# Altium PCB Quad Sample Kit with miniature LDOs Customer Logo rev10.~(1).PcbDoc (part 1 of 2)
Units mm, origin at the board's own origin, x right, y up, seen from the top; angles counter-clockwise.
Board outline 152.4 x 101.6 mm, 2 copper layers (Top Layer, Bottom Layer); 23 components, 21 nets, 109 pads, 47 vias.
Unrouted connection lines stored in the file: 13.
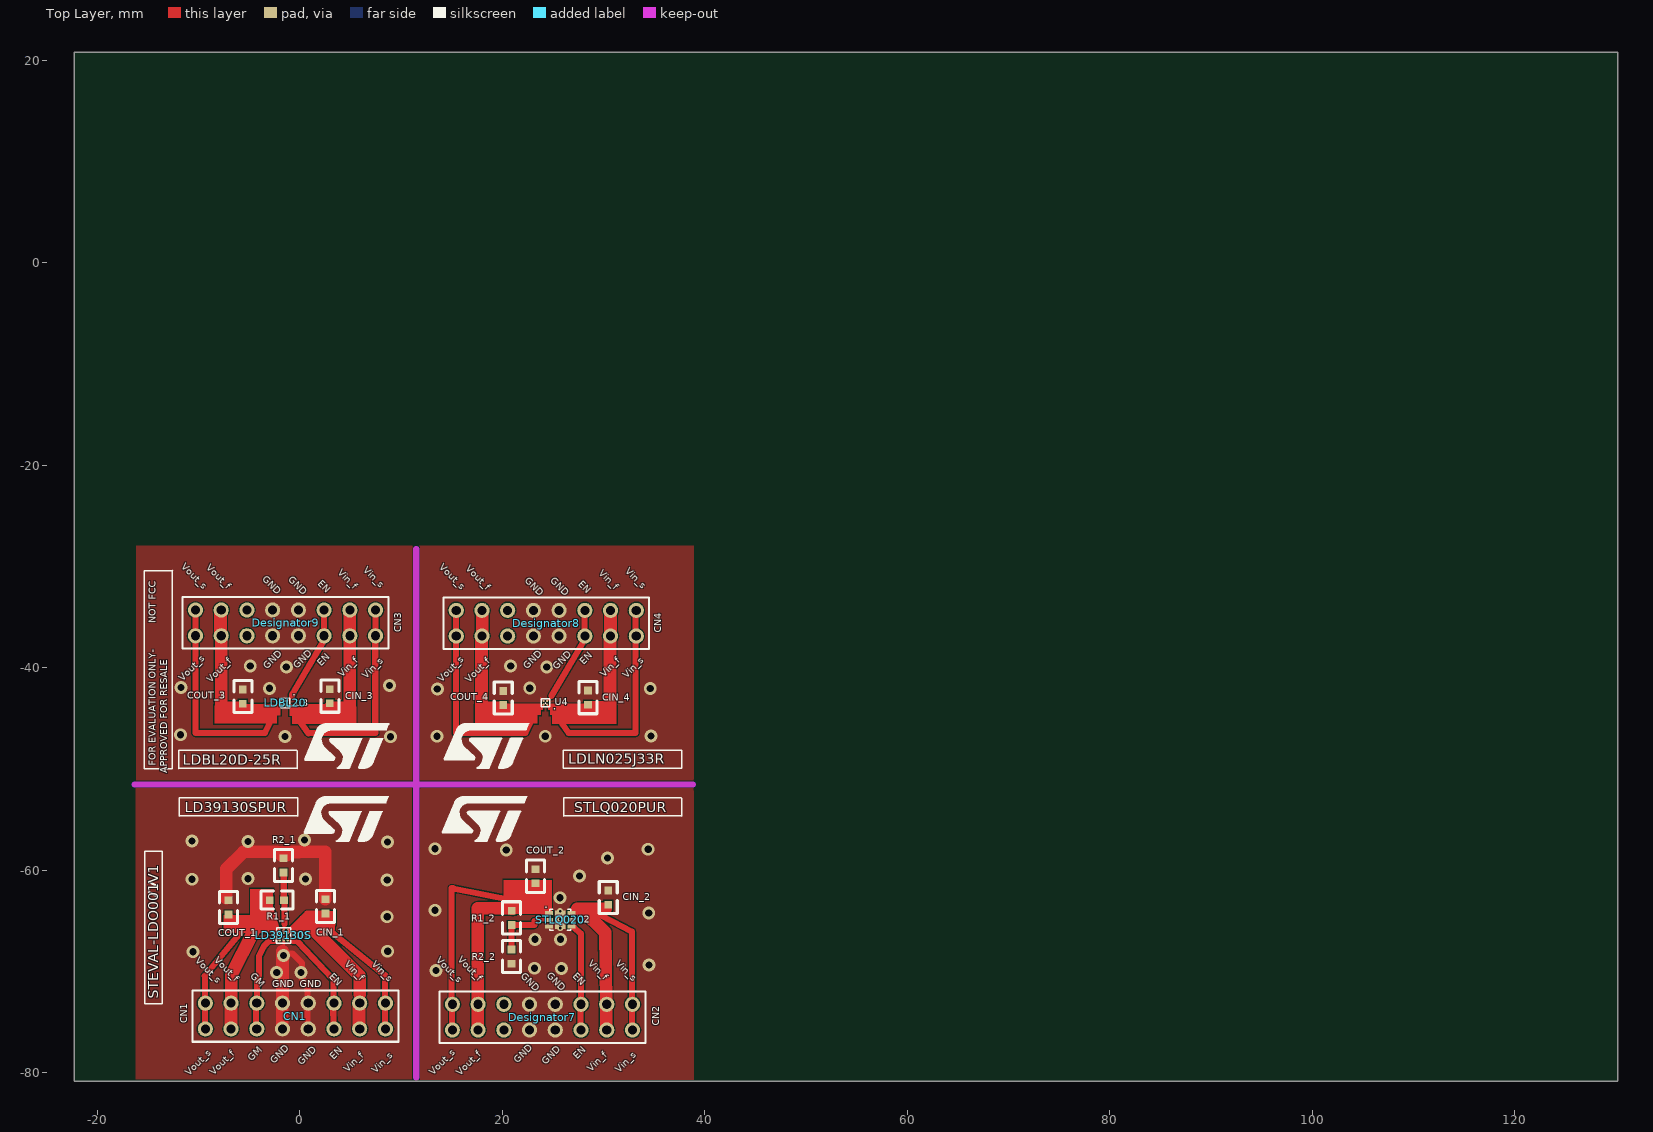
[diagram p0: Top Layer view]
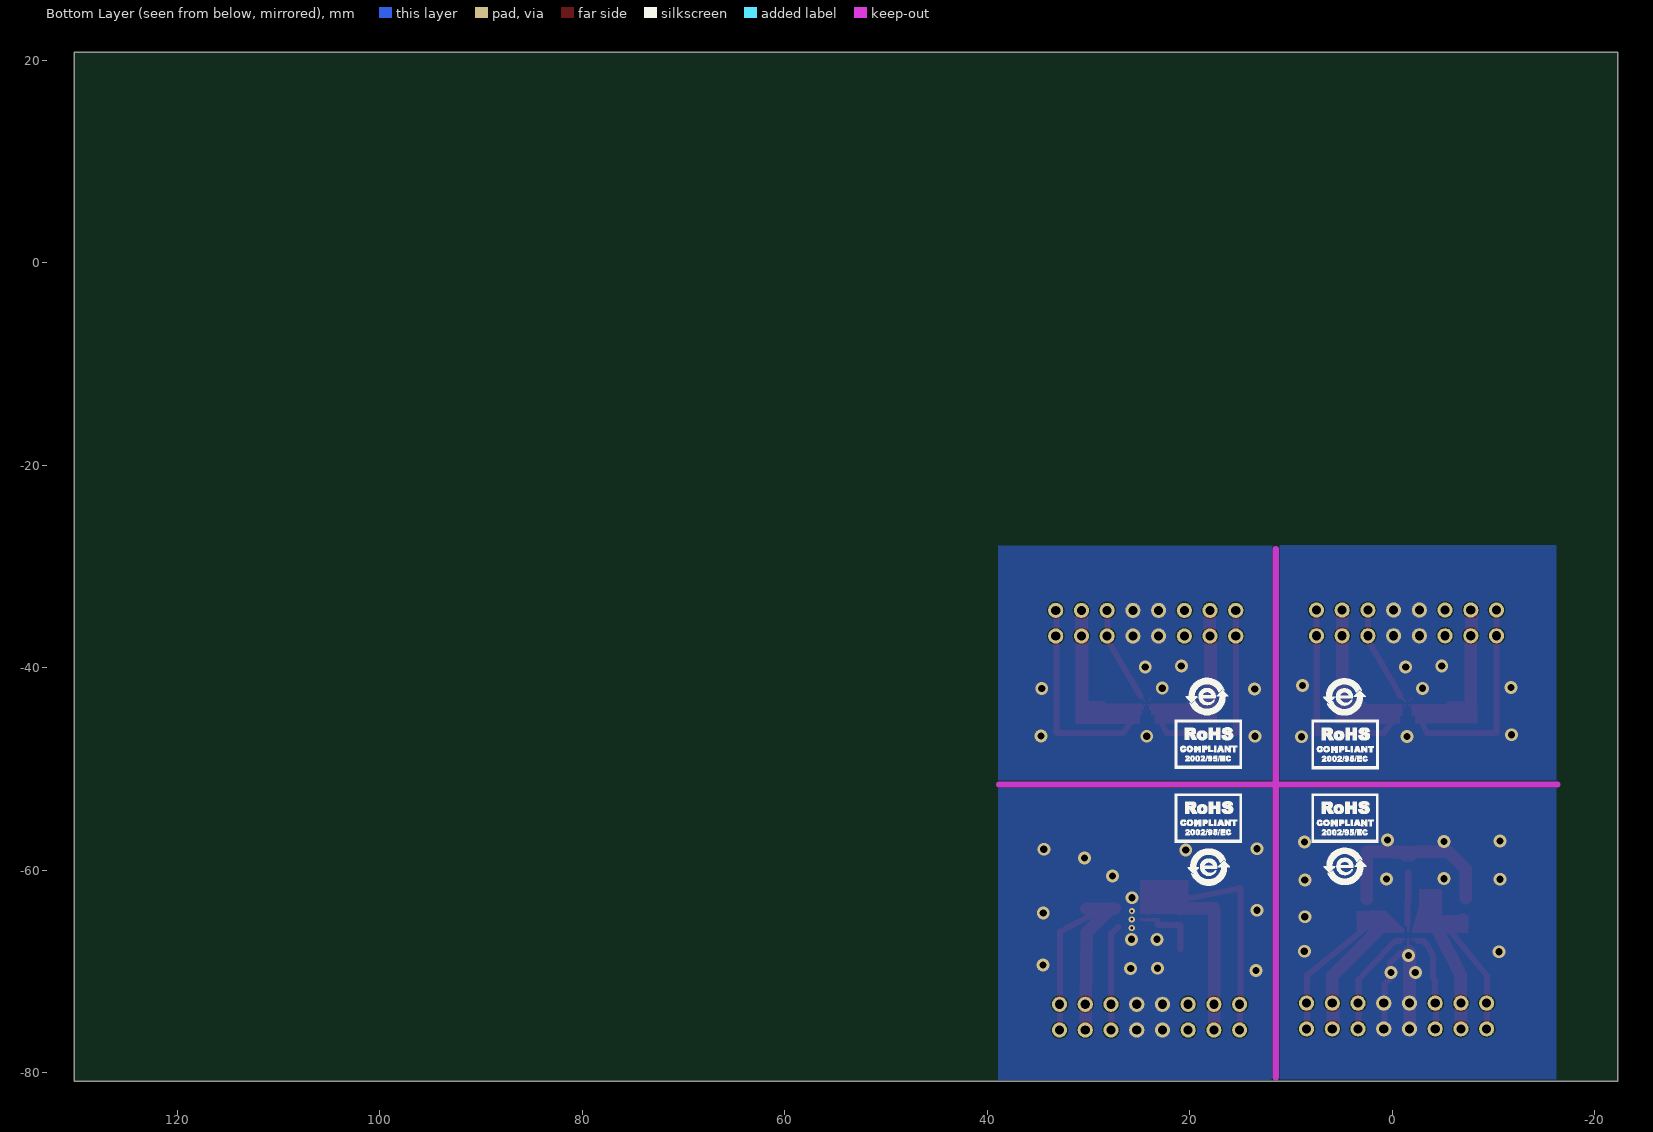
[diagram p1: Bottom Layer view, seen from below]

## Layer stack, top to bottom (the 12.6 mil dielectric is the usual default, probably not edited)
Top Layer: signal copper 0.0356
Dielectric: dielectric 0.32, FR-4, Dk 4.8
Bottom Layer: signal copper 0.0356

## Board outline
-22.247,-80.823 130.153,-80.823 130.153,20.777 -22.247,20.777

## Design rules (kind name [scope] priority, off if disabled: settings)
Clearance Clearance_1 [All] p1: gap=0.1
Clearance [All] p2: gap=0.1
ComponentClearance [All] p1: gap=0.254 collisioncheckmode=3 verticalgap=0.254
PolygonConnect [All] p1: connectstyle=Direct reliefconductorwidth=0.254 reliefentries=4 polygonreliefangle="90 Angle"
RoutingVias [All] p1: holewidth=0.711 width=1.27 viastyle="Through Hole" minholewidth=0.25 minwidth=0.25 maxholewidth=1 maxwidth=1.27
SolderMaskExpansion [All] p1: expansion=-0.035
TestPointUsage [All] p1: valid=0 allowmultiple=FALSE
Testpoint [All] p1: side=15 testpointundercomponent=TRUE minsize=1.016 maxsize=2.54 preferedsize=1.524 minholesize=0 maxholesize=1.016 preferedholesize=0.813 testpointgrid=0.025 style=1023 order=0123456789
Width [All] p1: maxlimit=2 minlimit=0.154 preferedwidth=0.254 minimp=50.000000 maximp=50.000000 favimp=50.000000
18 further rules are at their usual default settings.

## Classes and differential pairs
component class "Quad Sample Kit with miniature LDOs": CIN_1 CIN_2 CIN_3 CIN_4 Connector_1 Connector_2 Connector_3 Connector_4 COUT_1 COUT_2 COUT_3 COUT_4 LD39130S LDBL20 LDLN025J33R R1_1 R1_2 R2_1 R2_2 STLQ020

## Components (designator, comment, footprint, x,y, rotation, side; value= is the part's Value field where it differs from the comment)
CIN_1 "Cap" 0603 2.56,-63.562 r270 top
CIN_2 "Cap" 0603 30.478,-62.685 r270 top
CIN_3 "Cap" 0603 2.985,-42.804 r270 top
CIN_4 "Cap" 0603 28.472,-42.949 r270 top
CN1 "Comment" HDR2X8 -9.306,-75.655 r0 top
COUT_1 "Cap" 0603 -7.016,-63.664 r270 top
COUT_2 "Cap" 0603 23.284,-60.58 r270 top
COUT_3 "Cap" 0603 -5.608,-42.843 r270 top
COUT_4 "Cap" 0603 20.106,-42.983 r270 top
Designator7 "Comment" HDR2X8 15.086,-75.766 r0 top
Designator8 "Comment" HDR2X8 15.465,-36.867 r0 top
Designator9 "Comment" HDR2X8 -10.281,-36.84 r0 top
LD39130S "DFN6" PCBComponent_1#1 -1.178,-66.788 r0 top (schematic designator LD391303S)
LDBL20 "STSTAMP" PCBComponent_1#2 -1.253,-43.649 r0 top
R1_1 "Res1" 0603 -2.243,-62.939 r180 top
R1_2 "Res1" 0603 20.943,-64.692 r90 top
R2_1 "Res1" 0603 -1.585,-59.514 r270 top
R2_2 "Res1" 0603 20.923,-68.518 r270 top
STLQ020 "DFN6 2x2" PCBComponent_1#3 24.639,-64.882 r270 top
? "Comment" "LOGO_2014_10mm - duplicate" 13.544,-52.738 r0 top
? "Comment" "LOGO_2014_10mm - duplicate" 13.749,-45.529 r0 top
? "Comment" "LOGO_2014_10mm - duplicate" -0.11,-52.75 r0 top
? "Comment" "LOGO_2014_10mm - duplicate" -0.059,-45.55 r0 top

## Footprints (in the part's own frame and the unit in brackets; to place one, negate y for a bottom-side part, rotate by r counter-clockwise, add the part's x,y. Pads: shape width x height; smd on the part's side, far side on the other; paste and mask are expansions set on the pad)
0603 [mil]
  rect 30x30 smd: 1(-27.5,0) 2(27.48,0)
  silkscreen extent -63,-35 63,35
HDR2X8 [mm] "Connector; Header; 8x2 Position"
  round 1.5 hole 0.9: 1(0,0) 2(0,2.54) 3(2.54,0) 4(2.54,2.54) 5(5.08,0) 6(5.08,2.54) 7(7.62,0) 8(7.62,2.54) 9(10.16,0) 10(10.16,2.54) 11(12.7,0) 12(12.7,2.54) 13(15.24,0) 14(15.24,2.54) 15(17.78,0) 16(17.78,2.54)
  silkscreen extent -1.27,-1.27 19.05,3.81
"LOGO_2014_10mm - duplicate" [mm] "10mm sensa scritta"
  silkscreen extent 0.55,-4.37 8.89,0.07
PCBComponent_1#1 [mm]
  oct 0.25x0.475 smd: 0(-0.8,0) 0(-0.8,0.725) 0(-0.4,0) 0(-0.4,0.725) 0(0,0) 0(0,0.725)
PCBComponent_1#2 [mm]
  rect 0.25x0.25 smd: 0(-0.35,0) 0(-0.35,0.35) 0(0,0) 0(0,0.35)
PCBComponent_1#3 [mm]
  rect 0.4x0.8 smd: 0(-0.65,2.2) 0(-0.65,0) 0(0,2.2) 0(0,0) 0(0.65,2.2) 0(0.65,0)
  rect 1.8x1 smd: 1(0,1.1)

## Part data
CIN_1 CIN_2 CIN_3 CIN_4 COUT_1 COUT_2 COUT_3 COUT_4: "Capacitor"
CN1 Designator7 Designator8 Designator9: library part "Header 8X2"
LDBL20 STLQ020: library part Component_1
R1_1 R1_2 R2_1 R2_2: "Resistor"

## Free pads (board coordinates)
  round 0.181 smd: 1(24.094,-43.629) 1(24.094,-43.279) 1(24.444,-43.629) 1(24.444,-43.279)

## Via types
v1: diameter 1.27, hole 0.711, Top Layer to Bottom Layer, 44 vias
v2: diameter 0.6, hole 0.25, Top Layer to Bottom Layer, 3 vias

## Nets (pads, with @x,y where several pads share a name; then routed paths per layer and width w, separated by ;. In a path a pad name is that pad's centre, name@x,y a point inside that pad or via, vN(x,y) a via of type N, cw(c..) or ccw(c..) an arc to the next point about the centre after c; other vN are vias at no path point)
ADJ: LD39130S.0@-1.578,-66.063 R1_1.1 R1_2.1 R2_1.2 R2_2.1 STLQ020.0@24.639,-64.882 | length 15.1
  Top Layer w0.25: LD39130S.0@-1.577,-66.017 R1_1.1@-1.577,-62.989
  Top Layer w0.254: R1_1.1@-1.72,-62.717 -1.72,-62.681 R1_1.1@-1.72,-62.677 ; R1_1.1@-1.568,-62.941 -1.565,-62.932 R1_1.1@-1.555,-62.901 ; R1_2.1@20.822,-65.402 20.908,-65.382 R1_2.1@20.939,-65.375 ; R1_2.1@20.946,-65.39 20.946,-65.385 R1_2.1@20.946,-65.375 ; STLQ020.0@24.639,-64.869 STLQ020.0@24.813,-64.871
  Top Layer w0.35: 23.267,-64.875 STLQ020.0@24.637,-64.875
  Top Layer w0.6: R1_1.1@-1.568,-63.021 R2_1.2@-1.568,-60.194 ; R1_1.1@-1.568,-62.992 -1.479,-62.992 -1.479,-65.302 ; R1_2.1@20.909,-65.385 23.182,-65.385 23.182,-65.025 ; R2_2.1@20.928,-67.799 R1_2.1@20.928,-65.39
EN: CN1.11 CN1.12 Designator7.11 Designator7.12 Designator8.11 Designator8.12 Designator9.11 Designator9.12 LD39130S.0@-1.178,-66.788 LDBL20.0@-1.253,-43.299 pad.1@24.444,-43.279 STLQ020.0@26.839,-65.532 | length 40.9
  Top Layer w0.181: pad.1@24.444,-43.279 24.714,-43.015
  Top Layer w0.25: LDBL20.0@-1.253,-43.299 -0.668,-42.767
  Top Layer w0.254: LD39130S.0@-1.161,-66.787 -0.385,-66.787 ; -0.43,-66.779 -0.422,-66.788 ; Designator9.11@2.365,-37.305 Designator9.11@2.372,-37.303 ; Designator9.11@2.373,-37.303 2.395,-37.297 Designator9.11@2.408,-37.293 ; Designator9.11@2.381,-37.335 Designator9.11@2.381,-37.333 ; Designator9.11@2.393,-37.336 Designator9.11@2.398,-37.307 ; 3.34,-70.771 3.414,-70.85 ; STLQ020.0@26.893,-65.625 STLQ020.0@27.074,-65.61
  Top Layer w0.6: -0.771,-42.758 -0.732,-42.712 -0.718,-42.696 -0.648,-42.614 ; -0.757,-42.655 Designator9.11@2.388,-37.333 ; -0.715,-66.991 -0.216,-67.005 3.34,-70.77 ; Designator9.11@2.336,-36.796 Designator9.11@2.409,-36.723 ; Designator9.11@2.411,-36.774 Designator9.12@2.411,-34.312 ; CN1.12@3.322,-73.045 3.323,-73.116 CN1.11@3.343,-75.634 ; 3.339,-70.727 3.34,-70.77 ; CN1.12@3.347,-72.881 3.347,-72.85 3.34,-70.85 3.34,-70.771 ; 24.853,-42.796 Designator8.11@28.09,-37.318 ; STLQ020.0@27.074,-65.61 27.775,-66.257 Designator7.12@27.775,-72.98 ; Designator7.11@27.738,-75.77 Designator7.12@27.738,-73.252 ; Designator8.12@28.081,-34.249 Designator8.12@28.084,-34.33 ; Designator8.11@28.145,-36.873 Designator8.12@28.145,-34.336
GM: CN1.5 CN1.6 LD39130S.0@-1.978,-66.788 | length 10
  Top Layer w0.254: CN1.6@-4.215,-72.854 CN1.6@-4.215,-72.692 ; -2.507,-66.959 -2.465,-66.788 LD39130S.0@-1.997,-66.788
  Top Layer w0.6: CN1.5@-4.297,-75.634 -4.297,-73.116 CN1.6@-4.297,-73.108 ; CN1.6@-4.215,-72.692 -4.212,-70.809 -4.015,-70.612 -4.015,-68.466 ; -4.022,-68.55 -4.015,-68.535 -3.527,-67.491 -2.995,-66.959 -2.507,-66.959
GND: CIN_1.1 CIN_2.1 CIN_3.1 CIN_4.1 CN1.7 CN1.8 CN1.9 CN1.10 COUT_1.1 COUT_2.1 COUT_3.1 COUT_4.1 Designator7.7 Designator7.8 Designator7.9 Designator7.10 Designator8.7 Designator8.8 Designator8.9 Designator8.10 Designator9.7 Designator9.8 Designator9.9 Designator9.10 LD39130S.0@-1.578,-66.788 LDBL20.0@-1.603,-43.299 pad.1@24.094,-43.279 R2_1.1 R2_2.2 STLQ020.0@24.639,-65.532 STLQ020.1 | length 37.2
  Top Layer w0.181: -1.931,-42.984 LDBL20.0@-1.603,-43.299 ; 23.808,-42.986 pad.1@24.091,-43.276
  Top Layer w0.25: -1.578,-67.546 LD39130S.0@-1.578,-66.745
  Top Layer w0.254: COUT_1.1@-7.074,-62.979 -7.07,-62.972 COUT_1.1@-7.053,-62.944 ; COUT_1.1@-6.997,-63.018 -6.997,-62.98 COUT_1.1@-6.997,-62.966 ; CN1.8@-1.696,-72.851 CN1.8@-1.696,-72.847 ; R2_1.1@-1.604,-58.828 R2_1.1@-1.585,-58.828 ; R2_1.1@-1.601,-58.821 R2_1.1@-1.585,-58.821 ; CN1.8@-1.585,-72.919 -1.585,-72.898 -1.585,-72.85 CN1.8@-1.585,-72.847
  Top Layer w0.6: v1@-1.778,-68.202 -0.708,-68.202 0.25,-69.16 0.25,-70.723 0.795,-71.268 CN1.10@0.795,-72.914 ; CN1.10@0.77,-73.114 CN1.9@0.775,-75.571 ; CN1.10@0.818,-73.114 CN1.10@0.818,-73.087
  Top Layer w1.25: COUT_1.1@-7.238,-62.724 -7.238,-59.863 -5.552,-58.177 -2.245,-58.177 -2.225,-58.197 -0.711,-58.197 ; R2_1.1@-1.78,-58.518 -1.282,-58.518 -0.938,-58.174 ; CN1.8@-1.729,-73.108 -1.729,-73.115 CN1.7@-1.708,-75.634 ; CN1.8@-1.685,-72.803 v1@-1.685,-68.004 ; -0.925,-58.185 -0.064,-58.185 ; -0.064,-58.177 2.536,-58.177 ; CIN_1.1@2.536,-62.863 2.536,-58.328
  other v1: -2.266,-70.085 0.133,-70.091 13.475,-69.901 23.189,-69.661 25.845,-69.685 34.511,-69.353 -1.587,-68.403 -10.529,-68.035 8.695,-67.993 23.238,-66.81 25.772,-66.81 8.647,-64.576 34.48,-64.21 13.373,-63.938 25.713,-62.712 8.647,-60.944 -10.631,-60.879 0.577,-60.865 -5.09,-60.822 27.629,-60.56 30.393,-58.775 20.407,-57.979 34.418,-57.921 13.373,-57.872 8.671,-57.193 -5.085,-57.14 -10.631,-57.096 0.475,-57.002 8.965,-46.807 -1.456,-46.778 13.576,-46.759 24.253,-46.761 34.695,-46.74 -11.769,-46.615 13.599,-42.08 -2.984,-42.026 34.625,-42.038 22.725,-42.009 -11.718,-41.93 8.863,-41.737 -1.31,-39.933 24.399,-39.916 -4.868,-39.828 20.841,-39.811
  other v2: 25.736,-65.691 25.739,-64.846 25.728,-64.022
NetCIN_4_2: 
NetConnector_1_1: 
NetConnector_1_3: 
NetConnector_1_4: 
NetConnector_1_5: 
NetConnector_2_1: 
NetConnector_2_3: 
NetConnector_2_5: 
NetConnector_3_1: 
NetConnector_3_3: 
NetConnector_3_5: 
NetConnector_4_3: 
NetConnector_4_5: 
NetLD391303S_5: 
NetR1_2_1: 
Vin: CIN_1.2 CIN_2.2 CIN_3.2 CIN_4.2 CN1.13 CN1.14 CN1.15 CN1.16 Designator7.13 Designator7.14 Designator7.15 Designator7.16 Designator8.13 Designator8.14 Designator8.15 Designator8.16 Designator9.13 Designator9.14 Designator9.15 Designator9.16 LD39130S.0@-1.178,-66.063 LDBL20.0@-1.253,-43.649 pad.1@24.444,-43.629 STLQ020.0@26.839,-64.232 | length 125.9
  Top Layer w0.181: LDBL20.0@-1.253,-43.649 -0.917,-43.968 ; pad.1@24.444,-43.629 24.668,-43.86
  Top Layer w0.254: LD39130S.0@-1.072,-66.081 0.987,-66.081 ; 1.029,-66.081 1.602,-66.081
  Top Layer w0.6: -0.87,-65.898 0.743,-64.285 2.092,-64.285 ; -0.682,-44.266 0.867,-46.485 ; 0.909,-46.443 7.473,-46.443 7.473,-37.34 Designator9.15@7.472,-37.299 ; 2.371,-65.46 8.443,-70.376 8.455,-70.386 ; CIN_1.2@2.466,-64.336 CIN_1.2@2.56,-64.26 CIN_1.2@2.564,-64.257 ; 2.801,-44.172 2.971,-44.176 ; Designator9.13@4.924,-37.315 Designator9.13@4.924,-37.341 ; CN1.14@5.869,-73.116 CN1.14@5.869,-73.087 ; CN1.13@5.89,-75.718 CN1.13@5.889,-75.655 ; Designator9.15@7.507,-36.852 Designator9.16@7.507,-34.312 ; CN1.15@8.443,-75.441 8.443,-70.355 ; 25.027,-44.249 26.547,-46.426 33.182,-46.426 Designator8.15@33.182,-37.323 ; 28.51,-44.155 28.68,-44.159 ; 28.89,-64.011 32.817,-66.041 Designator7.16@32.817,-73.286 ; Designator7.14@30.27,-73.286 Designator7.14@30.271,-73.33 ; Designator7.14@30.298,-73.226 Designator7.14@30.298,-73.188 ; Designator8.13@30.747,-36.866 Designator8.13@30.747,-36.873 ; Designator7.15@32.837,-75.791 32.837,-75.766 Designator7.16@32.837,-73.226 ; Designator7.16@32.85,-73.313 Designator7.16@32.85,-73.286 ; Designator7.16@32.858,-73.226 Designator7.16@32.858,-73.209 ; Designator8.16@33.159,-34.27 33.161,-34.33 Designator8.15@33.161,-36.867 ; Designator8.15@33.244,-36.873 Designator8.15@33.244,-36.867
  Top Layer w1.25: 1.195,-65.674 5.932,-70.411 5.932,-72.215 ; 2.989,-43.936 4.94,-43.936 Designator9.13@4.94,-37.299 ; Designator9.13@4.946,-36.84 4.946,-34.3 Designator9.14@4.946,-34.261 ; CN1.13@5.869,-75.655 CN1.14@5.869,-73.116 ; Designator9.16@7.404,-34.301 Designator9.16@7.404,-34.286 ; Designator9.15@7.43,-36.841 Designator9.15@7.43,-36.872 ; 27.403,-63.802 30.244,-63.802 ; 27.958,-63.944 30.18,-66.111 30.269,-73.188 30.269,-73.227 Designator7.14@30.27,-73.286 ; CIN_4.2@28.698,-43.919 30.649,-43.919 Designator8.13@30.649,-37.282 ; Designator7.13@30.277,-75.728 Designator7.14@30.277,-73.226 ; Designator8.13@30.705,-36.867 Designator8.14@30.705,-34.327
Vout: CN1.1 CN1.2 CN1.3 CN1.4 COUT_1.2 COUT_2.2 COUT_3.2 COUT_4.2 Designator7.1 Designator7.2 Designator7.3 Designator7.4 Designator8.1 Designator8.2 Designator8.3 Designator8.4 Designator9.1 Designator9.2 Designator9.3 Designator9.4 LD39130S.0@-1.978,-66.063 LDBL20.0@-1.603,-43.649 pad.1@24.094,-43.629 R1_1.2 R1_2.2 STLQ020.0@24.639,-64.232 | length 136.4
  Top Layer w0.181: -2.005,-44.016 LDBL20.0@-1.603,-43.649 ; 23.888,-43.89 pad.1@24.094,-43.629
  Top Layer w0.254: COUT_1.2@-7.024,-64.337 -7.008,-64.343 -2.832,-66.05 -2.822,-66.054 ; CN1.4@-6.753,-72.872 CN1.4@-6.751,-72.846 ; -5.774,-66.081 -2.717,-66.081 ; -4.177,-66.081 -4.175,-66.08 ; R1_1.2@-2.915,-62.936 -2.832,-63.224 -2.022,-66.035 -2.717,-66.044 ; -2.832,-66.072 -2.832,-66.044 ; R1_1.2@-2.832,-62.939 R1_1.2@-2.832,-62.687
  Top Layer w0.6: Designator9.1@-10.285,-37.378 -10.285,-46.443 -3.424,-46.443 -2.314,-44.161 ; Designator9.1@-10.281,-36.84 Designator9.2@-10.281,-34.3 ; -9.365,-70.424 -5.774,-66.081 ; CN1.1@-9.342,-75.697 -9.342,-70.463 ; Designator7.2@15.013,-73.286 15.013,-61.769 ; Designator7.1@15.063,-75.791 15.063,-75.766 Designator7.2@15.063,-73.226 ; 15.13,-61.769 21.146,-62.992 ; Designator8.1@15.424,-37.361 15.424,-46.426 22.285,-46.426 23.395,-44.144 ; Designator8.1@15.427,-36.867 Designator8.2@15.427,-34.328
  Top Layer w1.25: Designator9.2@-10.262,-34.3 Designator9.2@-10.262,-34.286 ; Designator9.3@-7.804,-36.821 Designator9.4@-7.804,-34.286 ; Designator9.3@-7.753,-37.283 -7.753,-43.956 -5.772,-43.956 ; CN1.3@-6.78,-75.529 CN1.4@-6.78,-73.151 ; CN1.4@-6.751,-72.846 -6.751,-70.328 ; -6.751,-70.333 -4.566,-66.081 ; Designator8.2@15.427,-34.328 Designator8.2@15.427,-34.312 ; Designator8.1@15.47,-36.936 Designator8.1@15.469,-36.867 ; Designator7.3@17.581,-75.749 Designator7.4@17.581,-73.252 ; Designator7.4@17.588,-73.286 17.588,-63.744 ; 17.694,-63.744 R1_2.2@20.946,-63.744 ; Designator8.3@17.956,-37.266 17.956,-43.939 COUT_4.2@19.937,-43.939 ; Designator8.3@18.03,-36.936 Designator8.4@18.03,-34.355 ; R1_2.2@20.946,-63.803 R1_2.2@20.967,-63.803 ; 21.146,-62.992 23.974,-63.567 ; 23.974,-63.74 24.19,-63.74
pads on no net: Designator7.5 Designator7.6 Designator8.5 Designator8.6 Designator9.5 Designator9.6 STLQ020.0@26.839,-64.882

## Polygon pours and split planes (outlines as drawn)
GND on Top Layer "Top Layer-GND 1" (solid, remove dead copper, pour order 1000): 38.942,-51.167 38.942,-27.958 11.776,-27.958 11.776,-51.191 38.966,-51.191
GND on Top Layer "Top Layer-GND" (solid, remove dead copper, pour order 1000): 11.197,-51.173 -16.121,-51.173 -16.121,-27.964 11.197,-27.964
GND on Top Layer "Top Layer-GND 2" (solid, remove dead copper, pour order 1000): -16.221,-51.899 11.08,-51.899 11.08,-80.637 -16.174,-80.637 -16.174,-51.899
GND on Top Layer "Top Layer-GND 3" (solid, remove dead copper, pour order 1001): 11.961,-51.899 38.937,-51.899 38.937,-80.674 11.915,-80.674 11.915,-51.946
GND on Bottom Layer "Bottom Layer-GND" (solid, remove dead copper, pour order 1001): 11.103,-51.145 -16.163,-51.145 -16.163,-27.903 11.142,-27.903 11.142,-51.106
GND on Bottom Layer "Bottom Layer-GND 3" (solid, remove dead copper, pour order 1007): 11.125,-51.859 -16.162,-51.859 -16.162,-80.615 11.125,-80.615
GND on Bottom Layer "Bottom Layer-GND 2" (solid, remove dead copper, pour order 1006): 11.859,-51.859 38.905,-51.859 38.905,-80.685 11.859,-80.685
GND on Bottom Layer "Bottom Layer-GND 1" (solid, remove dead copper, pour order 1001): 38.938,-51.166 38.938,-27.928 11.818,-27.928 11.818,-51.166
